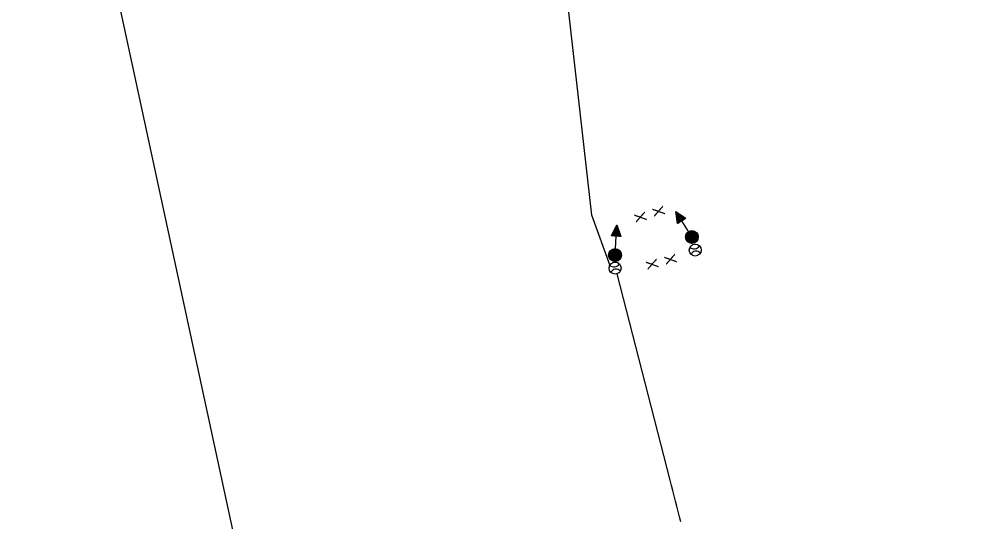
# Model space of a CAD drawing. Extents: x 601462 to 605493, y 331960 to 402715.
# Drawn here: x 601542 to 602143, y 354887 to 355203 of the extents above; entities that cross this region are included whole.
import ezdxf

# ---------------------------------------------------------------- set-up
doc = ezdxf.new("R2010")
doc.units = 0
for name, color, linetype in [('Default', 7, 'Continuous'), ('E_FTMS', 7, 'Continuous'), ('P_FTMS', 7, 'Continuous'), ('P_FTMSConduit', 7, 'Continuous'), ('P_MISC_TXT_2B (Construction)', 7, 'Continuous')]:
    doc.layers.add(name, color=color, linetype=linetype)

# ---------------------------------------------------------------- blocks, each defined once
blk = doc.blocks.new('POINT_DISPLAY')
at = {"layer": 'Default'}
blk.add_line((0, 0), (0, 0), dxfattribs=at)
blk = doc.blocks.new('FSGL')
at = {"layer": 'P_FTMS'}
for p, q in [((-114.3, -0.6), (-112.1, 1.6)), ((-112.1, -1.6), (-114.3, 0.6)), ((-112.8, -1.3), (-108.3, 3.2)), ((-108.3, -3.2), (-112.8, 1.3)), ((-111.3, -1.9), (-104.5, 4.8)), ((-104.5, -4.8), (-111.3, 1.9)), ((-109.8, -2.6), (-100.7, 6.5)), ((-100.7, -6.5), (-109.8, 2.6)), ((-108.3, -3.2), (-97, 8.1)), ((-97, -8.1), (-108.3, 3.2)), ((-106.8, -3.9), (-93.2, 9.7)), ((-93.2, -9.7), (-106.8, 3.9)), ((-105.3, -4.5), (-89.4, 11.3)), ((-89.4, -11.3), (-105.3, 4.5)), ((-103.8, -5.2), (-85.7, 12.9)), ((-85.7, -12.9), (-103.8, 5.2)), ((-102.2, -5.8), (-81.9, 14.5)), ((-81.9, -14.5), (-102.2, 5.8)), ((-100.7, -6.5), (-78.1, 16.2)), ((-78.1, -16.2), (-100.7, 6.5)), ((-99.2, -7.1), (-74.3, 17.8)), ((-74.3, -17.8), (-99.2, 7.1)), ((-97.7, -7.8), (-73.2, 16.8)), ((-73.2, -16.8), (-97.7, 7.8)), ((-96.2, -8.4), (-73.2, 14.7)), ((-73.2, -14.7), (-96.2, 8.4)), ((-94.7, -9.1), (-73.2, 12.5)), ((-73.2, -12.5), (-94.7, 9.1)), ((-93.2, -9.7), (-73.2, 10.3)), ((-73.2, -10.3), (-93.2, 9.7)), ((-73.2, -8.2), (-91.7, 10.3)), ((-91.7, -10.3), (-73.2, 8.2)), ((-73.2, -6), (-90.2, 11)), ((-90.2, -11), (-73.2, 6)), ((-73.2, -3.9), (-88.7, 11.6)), ((-88.7, -11.6), (-73.2, 3.9)), ((-73.2, -1.7), (-87.2, 12.3)), ((-87.2, -12.3), (-73.2, 1.7)), ((-73.2, 0.4), (-85.7, 12.9)), ((-73.2, 2.6), (-84.1, 13.6)), ((-73.2, 4.7), (-82.6, 14.2)), ((-73.2, 6.9), (-81.1, 14.9)), ((-73.2, 9.1), (-79.6, 15.5)), ((-73.2, 11.2), (-78.1, 16.2)), ((-73.2, 13.4), (-76.6, 16.8)), ((-73.2, 15.5), (-75.1, 17.5)), ((-73.2, 17.7), (-73.6, 18.1)), ((-24.6, 0), (-73.2, 0)), ((-24.3, -1.5), (1.5, 24.3)), ((-24.3, 0.5), (-0.5, 24.3)), ((1.5, -24.3), (-24.3, 1.5)), ((-24.1, -3.4), (3.4, 24.1)), ((-24.1, 2.8), (-2.7, 24.1)), ((3.4, -24.1), (-24.1, 3.4)), ((-23.8, -5.1), (5.1, 23.8)), ((-23.8, 5.1), (-5.2, 23.7)), ((5.1, -23.8), (-23.8, 5.2)), ((-23.4, -6.8), (6.8, 23.3)), ((6.8, -23.4), (-23.3, 6.8)), ((-22.9, 8.1), (-8, 23)), ((-22.8, -8.3), (8.4, 22.9)), ((8.3, -22.8), (-22.8, 8.4)), ((9.9, -22.3), (-22.3, 9.8)), ((-22.2, -9.8), (9.8, 22.2)), ((-21.6, -11.3), (11.2, 21.6)), ((11.2, -21.6), (-21.6, 11.2)), ((-21.2, 11.9), (-11.8, 21.4)), ((12.5, -20.8), (-20.9, 12.6)), ((-20.8, -12.5), (12.6, 20.8)), ((-20, -13.8), (13.8, 20)), ((13.8, -20), (-20, 13.8)), ((-19.2, -15), (15, 19.2)), ((15, -19.1), (-19.1, 15)), ((-18.2, -16.1), (16.1, 18.2)), ((16.1, -18.2), (-18.2, 16.2)), ((-17.2, -17.2), (17.2, 17.2)), ((17.2, -17.2), (-17.2, 17.2)), ((18.2, -16.1), (-16.1, 18.2)), ((-16.1, -18.2), (18.2, 16.2)), ((19.2, -15), (-15, 19.2)), ((-15, -19.1), (19.1, 15)), ((20, -13.8), (-13.8, 20)), ((-13.8, -20.1), (20, 13.8)), ((20.8, -12.5), (-12.6, 20.8)), ((-12.5, -20.8), (20.9, 12.6)), ((21.6, -11.3), (-11.2, 21.6)), ((-11.2, -21.6), (21.6, 11.2)), ((-9.9, -22.3), (22.2, 9.8)), ((22.2, -9.8), (-9.8, 22.2)), ((22.8, -8.3), (-8.4, 22.9)), ((-8.3, -22.8), (22.9, 8.4)), ((23.4, -6.8), (-6.8, 23.3)), ((-6.8, -23.4), (23.3, 6.8)), ((23.8, -5.1), (-5.1, 23.8)), ((-5.1, -23.8), (23.8, 5.2)), ((24.1, -3.4), (-3.4, 24.1)), ((-3.4, -24.1), (24.1, 3.4)), ((24.3, -1.5), (-1.5, 24.3)), ((-1.5, -24.3), (24.3, 1.5)), ((24.3, 0.5), (0.5, 24.3)), ((24.1, 2.8), (2.7, 24.1)), ((23.8, 5.1), (5.2, 23.8)), ((22.9, 8.1), (8, 23)), ((21.2, 11.9), (11.8, 21.3)), ((-85.7, -12.9), (-73.2, -0.4)), ((-84.1, -13.6), (-73.2, -2.6)), ((-82.6, -14.2), (-73.2, -4.7)), ((-81.1, -14.9), (-73.2, -6.9)), ((-79.6, -15.5), (-73.2, -9.1)), ((-78.1, -16.2), (-73.2, -11.2)), ((-76.6, -16.8), (-73.2, -13.4)), ((-75.1, -17.5), (-73.2, -15.5)), ((-73.6, -18.1), (-73.2, -17.7)), ((-0.5, -24.3), (-24.3, -0.5)), ((-2.7, -24.2), (-24.2, -2.7)), ((-5.2, -23.8), (-23.7, -5.2)), ((-8.1, -22.9), (-22.9, -8.1)), ((-12, -21.2), (-21.2, -11.9)), ((0.5, -24.3), (24.3, -0.5)), ((2.7, -24.2), (24.2, -2.7)), ((5.2, -23.8), (23.7, -5.2)), ((8.1, -22.9), (22.9, -8.1)), ((12, -21.2), (21.2, -11.9))]:
    blk.add_line(p, q, dxfattribs=at)
blk.add_lwpolyline([(-73.2, -18.3), (-115.8, 0), (-73.2, 18.3)], close=True, dxfattribs=at)
blk.add_circle((0, 0), 24.4, dxfattribs=at)
blk.add_blockref('POINT_DISPLAY', (-115.8, 0), dxfattribs=at)

msp = doc.modelspace()

# ---------------------------------------------------------------- linework, layer by layer
at = {"layer": 'P_FTMS'}
for centre in [(601967.2, 355057.43), (601916.91, 355046.11)]:
    msp.add_circle(centre, 3.75, dxfattribs=at)
for centre, start, end in [((601966.6, 355061.89), 224.54439, 330.80004), ((601967.8, 355052.97), 44.54439, 150.80004), ((601916.3, 355050.57), 224.54439, 330.80004), ((601917.51, 355041.65), 44.54439, 150.80004)]:
    msp.add_arc(centre, 3.75, start, end, dxfattribs=at)
at = {"layer": 'P_FTMSConduit'}
for p, q in [((601902.2, 355079.35), (601882.6, 355252.12)), ((601913.72, 355047.54), (601902.2, 355079.35))]:
    msp.add_line(p, q, dxfattribs=at)
msp.add_lwpolyline([(601951.45, 354912.77), (601918.13, 355042.42)], dxfattribs=at)
msp.add_arc((600711.62, 354577.97), 1284.25, 13.9064, 15.11153, dxfattribs=at)
at = {"layer": 'P_MISC_TXT_2B (Construction)'}
msp.add_lwpolyline([(602827.66, 354169.05), (602495.48, 355708.62), (601542.42, 355502.99), (601874.59, 353963.42)], close=True, dxfattribs=at)

# ---------------------------------------------------------------- block references
at = {"layer": 'E_FTMS'}
for p, xscale, yscale, rotation in [((601965.15, 355065.68), 0.16404165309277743, 0.16404165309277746, -57.59906443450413), ((601916.84, 355054.27), 0.16404164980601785, 0.16404164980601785, -93.35166671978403)]:
    msp.add_blockref('FSGL', p, dxfattribs=dict(at, xscale=xscale, yscale=yscale, rotation=rotation))

# ---------------------------------------------------------------- texts
at = {"layer": 'P_FTMSConduit'}
for p in [(601948.42, 355079.63), (601937, 355075.96), (601944.36, 355046.35), (601955.89, 355049.4)]:
    msp.add_text('X', height=7, rotation=104.38506, dxfattribs=at).set_placement(p)

doc.saveas('drawing.dxf')
